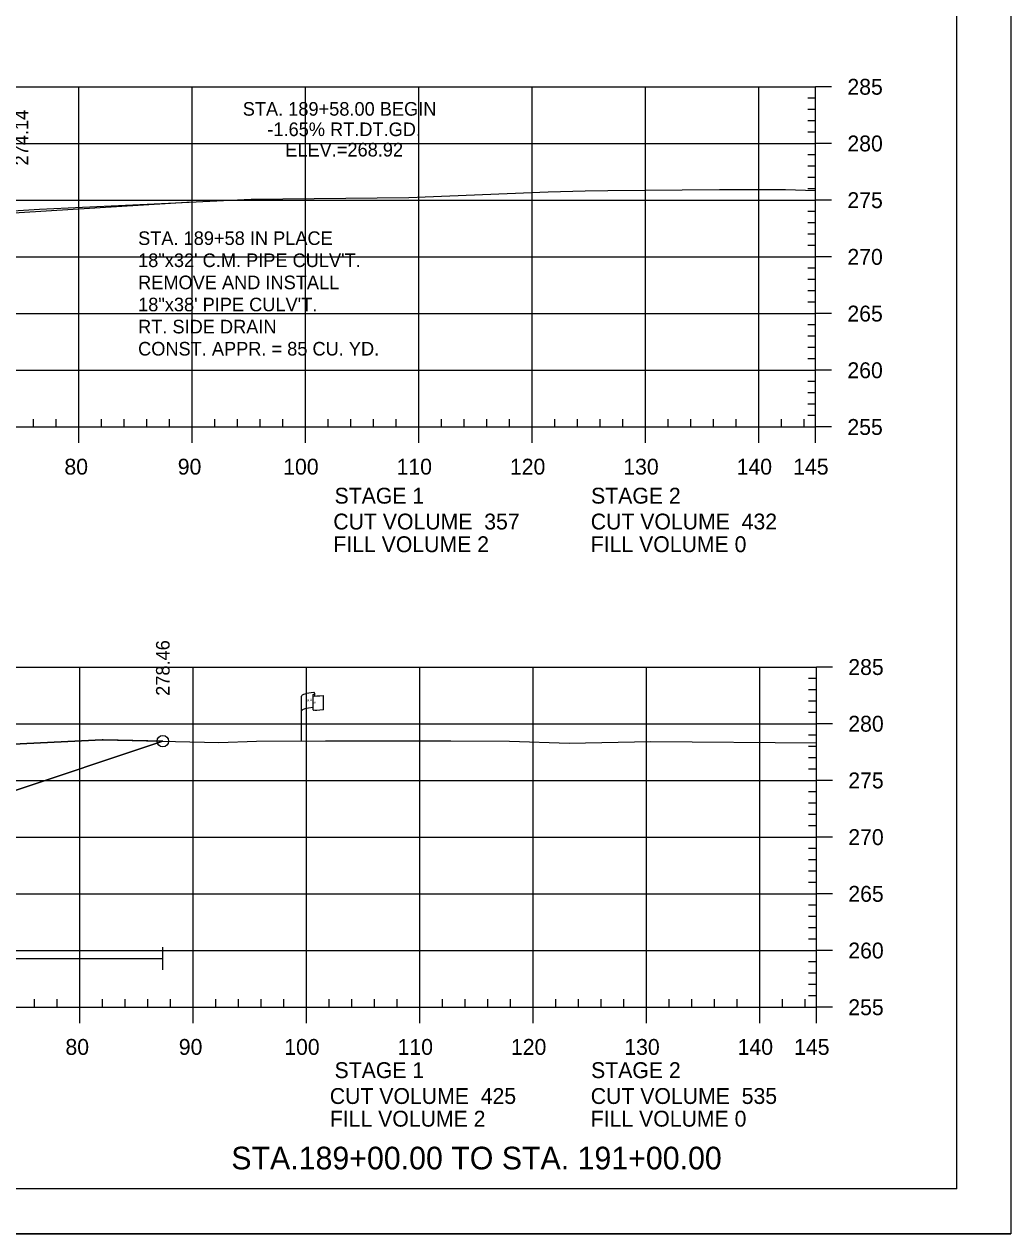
# Model space of a CAD drawing. Extents: x 1365647 to 1367999, y 387113 to 400173.
# Drawn here: x 1365970 to 1366057, y 388866.1 to 388972.8 of the extents above; entities that cross this region are included whole.
import ezdxf

# ---------------------------------------------------------------- set-up
doc = ezdxf.new("R2010")
doc.units = 0
for name, color, linetype in [('E_Existing ROW', 7, 'Continuous'), ('R_Axis', 7, 'Continuous'), ('R_Axis Annot', 7, 'Continuous'), ('R_Border', 7, 'Continuous'), ('R_Contours', 7, 'Continuous'), ('R_Draft', 7, 'Continuous'), ('R_Drive', 7, 'Continuous'), ('R_Exist Surface', 7, 'Continuous'), ('R_Fin Surface', 7, 'Continuous'), ('R_Fin Surface Annot', 7, 'Continuous'), ('R_Grid', 7, 'Continuous'), ('R_No Plot', 7, 'Continuous'), ('R_Proposed Const Limits', 7, 'Continuous'), ('R_Water', 7, 'Continuous')]:
    doc.layers.add(name, color=color, linetype=linetype)

msp = doc.modelspace()

# ---------------------------------------------------------------- linework, layer by layer
at = {"layer": 'E_Existing ROW'}
for p, q in [((1365994.45, 388909.56), (1365994.45, 388913.51)), ((1365995.45, 388913.6), (1365995.45, 388913.59)), ((1365995.45, 388913.59), (1365995.45, 388912.36)), ((1365995.61, 388913.76), (1365995.61, 388913.52)), ((1365996.38, 388913.56), (1365996.38, 388912.32))]:
    msp.add_line(p, q, dxfattribs=at)
for centre, radius, start, end in [((1365995.52, 388913.6), 0.078, 88.6458, 274.2828), ((1365995.54, 388913.76), 0.0783, 263.0712, 93.9564), ((1365995.53, 388912.36), 0.0783, 180, 273.9564)]:
    msp.add_arc(centre, radius, start, end, dxfattribs=at)
for centre, major_axis, ratio, start_param, end_param in [((1365996.03, 388913.55), (-1.58, -0.04), 0.19887, 5.030368, 6.283185), ((1365996.74, 388913.67), (-1.23, -0.13), 0.052933, 0.159456, 1.268315), ((1365996.03, 388912.23), (-1.58, -0.04), 0.19887, 5.083035, 6.194897), ((1365996.74, 388912.43), (-1.23, -0.13), 0.052933, 0.159456, 1.268315)]:
    msp.add_ellipse(centre, major_axis=major_axis, ratio=ratio, start_param=start_param, end_param=end_param, dxfattribs=at)
at = {"layer": 'R_Axis'}
for p, q in [((1366039.81, 388937.25), (1366039.81, 388967.25)), ((1366041.21, 388967.25), (1366039.81, 388967.25)), ((1366039.81, 388966.25), (1366039.11, 388966.25)), ((1366039.81, 388965.25), (1366039.11, 388965.25)), ((1366039.81, 388964.25), (1366039.11, 388964.25)), ((1366039.81, 388963.25), (1366039.11, 388963.25)), ((1366041.21, 388962.25), (1366039.81, 388962.25)), ((1366039.81, 388961.25), (1366039.11, 388961.25)), ((1366039.81, 388960.25), (1366039.11, 388960.25)), ((1366039.81, 388959.25), (1366039.11, 388959.25)), ((1366039.81, 388958.25), (1366039.11, 388958.25)), ((1366041.21, 388957.25), (1366039.81, 388957.25)), ((1366039.81, 388956.25), (1366039.11, 388956.25)), ((1366039.81, 388955.25), (1366039.11, 388955.25)), ((1366039.81, 388954.25), (1366039.11, 388954.25)), ((1366039.81, 388953.25), (1366039.11, 388953.25)), ((1366041.21, 388952.25), (1366039.81, 388952.25)), ((1366039.81, 388951.25), (1366039.11, 388951.25)), ((1366039.81, 388950.25), (1366039.11, 388950.25)), ((1366039.81, 388949.25), (1366039.11, 388949.25)), ((1366039.81, 388948.25), (1366039.11, 388948.25)), ((1366041.21, 388947.25), (1366039.81, 388947.25)), ((1366039.81, 388946.25), (1366039.11, 388946.25)), ((1366039.81, 388945.25), (1366039.11, 388945.25)), ((1366039.81, 388944.25), (1366039.11, 388944.25)), ((1366039.81, 388943.25), (1366039.11, 388943.25)), ((1366041.21, 388942.25), (1366039.81, 388942.25)), ((1366039.81, 388941.25), (1366039.11, 388941.25)), ((1366039.81, 388940.25), (1366039.11, 388940.25)), ((1366039.81, 388939.25), (1366039.11, 388939.25)), ((1365970.81, 388937.25), (1365970.81, 388937.95)), ((1365972.81, 388937.25), (1365972.81, 388937.95)), ((1365976.81, 388937.25), (1365976.81, 388937.95)), ((1365978.81, 388937.25), (1365978.81, 388937.95)), ((1365980.81, 388937.25), (1365980.81, 388937.95)), ((1365982.81, 388937.25), (1365982.81, 388937.95)), ((1365986.81, 388937.25), (1365986.81, 388937.95)), ((1365988.81, 388937.25), (1365988.81, 388937.95)), ((1365990.81, 388937.25), (1365990.81, 388937.95)), ((1365992.81, 388937.25), (1365992.81, 388937.95)), ((1365996.81, 388937.25), (1365996.81, 388937.95)), ((1365998.81, 388937.25), (1365998.81, 388937.95)), ((1366000.81, 388937.25), (1366000.81, 388937.95)), ((1366002.81, 388937.25), (1366002.81, 388937.95)), ((1366006.81, 388937.25), (1366006.81, 388937.95)), ((1366008.81, 388937.25), (1366008.81, 388937.95)), ((1366010.81, 388937.25), (1366010.81, 388937.95)), ((1366012.81, 388937.25), (1366012.81, 388937.95)), ((1366016.81, 388937.25), (1366016.81, 388937.95)), ((1366018.81, 388937.25), (1366018.81, 388937.95)), ((1366020.81, 388937.25), (1366020.81, 388937.95)), ((1366022.81, 388937.25), (1366022.81, 388937.95)), ((1366026.81, 388937.25), (1366026.81, 388937.95)), ((1366028.81, 388937.25), (1366028.81, 388937.95)), ((1366030.81, 388937.25), (1366030.81, 388937.95)), ((1366032.81, 388937.25), (1366032.81, 388937.95)), ((1366036.81, 388937.25), (1366036.81, 388937.95)), ((1366038.81, 388937.25), (1366038.81, 388937.95)), ((1366039.81, 388938.25), (1366039.11, 388938.25)), ((1365749.81, 388937.25), (1366039.81, 388937.25)), ((1365974.81, 388935.85), (1365974.81, 388937.25)), ((1365984.81, 388935.85), (1365984.81, 388937.25)), ((1365994.81, 388935.85), (1365994.81, 388937.25)), ((1366004.81, 388935.85), (1366004.81, 388937.25)), ((1366014.81, 388935.85), (1366014.81, 388937.25)), ((1366024.81, 388935.85), (1366024.81, 388937.25)), ((1366034.81, 388935.85), (1366034.81, 388937.25)), ((1366039.81, 388935.85), (1366039.81, 388937.25)), ((1366041.21, 388937.25), (1366039.81, 388937.25)), ((1366039.89, 388886.08), (1366039.89, 388916.08)), ((1366041.29, 388916.08), (1366039.89, 388916.08)), ((1366039.89, 388915.08), (1366039.19, 388915.08)), ((1366039.89, 388914.08), (1366039.19, 388914.08)), ((1366039.89, 388913.08), (1366039.19, 388913.08)), ((1366039.89, 388912.08), (1366039.19, 388912.08)), ((1366041.29, 388911.08), (1366039.89, 388911.08)), ((1366039.89, 388910.08), (1366039.19, 388910.08)), ((1366039.89, 388909.08), (1366039.19, 388909.08)), ((1366039.89, 388908.08), (1366039.19, 388908.08)), ((1366039.89, 388907.08), (1366039.19, 388907.08)), ((1366041.29, 388906.08), (1366039.89, 388906.08)), ((1366039.89, 388905.08), (1366039.19, 388905.08)), ((1366039.89, 388904.08), (1366039.19, 388904.08)), ((1366039.89, 388903.08), (1366039.19, 388903.08)), ((1366039.89, 388902.08), (1366039.19, 388902.08)), ((1366041.29, 388901.08), (1366039.89, 388901.08)), ((1366039.89, 388900.08), (1366039.19, 388900.08)), ((1366039.89, 388899.08), (1366039.19, 388899.08)), ((1366039.89, 388898.08), (1366039.19, 388898.08)), ((1366039.89, 388897.08), (1366039.19, 388897.08)), ((1366041.29, 388896.08), (1366039.89, 388896.08)), ((1366039.89, 388895.08), (1366039.19, 388895.08)), ((1366039.89, 388894.08), (1366039.19, 388894.08)), ((1366039.89, 388893.08), (1366039.19, 388893.08)), ((1366039.89, 388892.08), (1366039.19, 388892.08)), ((1366041.29, 388891.08), (1366039.89, 388891.08)), ((1366039.89, 388890.08), (1366039.19, 388890.08)), ((1366039.89, 388889.08), (1366039.19, 388889.08)), ((1366039.89, 388888.08), (1366039.19, 388888.08)), ((1365970.89, 388886.08), (1365970.89, 388886.78)), ((1365972.89, 388886.08), (1365972.89, 388886.78)), ((1365976.89, 388886.08), (1365976.89, 388886.78)), ((1365978.89, 388886.08), (1365978.89, 388886.78)), ((1365980.89, 388886.08), (1365980.89, 388886.78)), ((1365982.89, 388886.08), (1365982.89, 388886.78)), ((1365986.89, 388886.08), (1365986.89, 388886.78)), ((1365988.89, 388886.08), (1365988.89, 388886.78)), ((1365990.89, 388886.08), (1365990.89, 388886.78)), ((1365992.89, 388886.08), (1365992.89, 388886.78)), ((1365996.89, 388886.08), (1365996.89, 388886.78)), ((1365998.89, 388886.08), (1365998.89, 388886.78)), ((1366000.89, 388886.08), (1366000.89, 388886.78)), ((1366002.89, 388886.08), (1366002.89, 388886.78)), ((1366006.89, 388886.08), (1366006.89, 388886.78)), ((1366008.89, 388886.08), (1366008.89, 388886.78)), ((1366010.89, 388886.08), (1366010.89, 388886.78)), ((1366012.89, 388886.08), (1366012.89, 388886.78)), ((1366016.89, 388886.08), (1366016.89, 388886.78)), ((1366018.89, 388886.08), (1366018.89, 388886.78)), ((1366020.89, 388886.08), (1366020.89, 388886.78)), ((1366022.89, 388886.08), (1366022.89, 388886.78)), ((1366026.89, 388886.08), (1366026.89, 388886.78)), ((1366028.89, 388886.08), (1366028.89, 388886.78)), ((1366030.89, 388886.08), (1366030.89, 388886.78)), ((1366032.89, 388886.08), (1366032.89, 388886.78)), ((1366036.89, 388886.08), (1366036.89, 388886.78)), ((1366038.89, 388886.08), (1366038.89, 388886.78)), ((1366039.89, 388887.08), (1366039.19, 388887.08)), ((1365749.89, 388886.08), (1366039.89, 388886.08)), ((1365974.89, 388884.68), (1365974.89, 388886.08)), ((1365984.89, 388884.68), (1365984.89, 388886.08)), ((1365994.89, 388884.68), (1365994.89, 388886.08)), ((1366004.89, 388884.68), (1366004.89, 388886.08)), ((1366014.89, 388884.68), (1366014.89, 388886.08)), ((1366024.89, 388884.68), (1366024.89, 388886.08)), ((1366034.89, 388884.68), (1366034.89, 388886.08)), ((1366039.89, 388884.68), (1366039.89, 388886.08)), ((1366041.29, 388886.08), (1366039.89, 388886.08))]:
    msp.add_line(p, q, dxfattribs=at)
at = {"layer": 'R_Border'}
for q in [(1366052.27, 389075.54), (1365736.09, 388870.08)]:
    msp.add_line((1366052.27, 388870.08), q, dxfattribs=at)
at = {"layer": 'R_Contours'}
msp.add_line((1365982.22, 388909.54), (1365976.97, 388909.65), dxfattribs=at)
msp.add_lwpolyline([(1365927.05, 388902.69), (1365927.14, 388902.71), (1365929.49, 388903.28), (1365934.03, 388904.39), (1365942.29, 388905.41), (1365942.8, 388905.47), (1365946.8, 388906.16), (1365963.96, 388909.17), (1365969.03, 388909.29), (1365976.87, 388909.65), (1365976.94, 388909.65), (1365976.97, 388909.65), (1365982.22, 388909.54), (1365954.38, 388900.26), (1365941.51, 388902.41)], close=True, dxfattribs=at)
for points in [[(1365976.97, 388909.65), (1365976.94, 388909.65), (1365976.87, 388909.65), (1365969.03, 388909.29), (1365963.96, 388909.17), (1365946.8, 388906.16), (1365942.8, 388905.47), (1365942.29, 388905.41), (1365934.03, 388904.39), (1365932.18, 388903.93)], [(1365932.38, 388903.93), (1365941.51, 388902.41), (1365954.38, 388900.26), (1365982.22, 388909.54)], [(1365982.22, 388909.54), (1365982.22, 388909.54)]]:
    msp.add_lwpolyline(points, dxfattribs=at)
at = {"layer": 'R_Drive'}
msp.add_line((1365949.29, 388954.95), (1365984.81, 388957.09), dxfattribs=at)
at = {"layer": 'R_Exist Surface'}
for points in [[(1365961.93, 388955.88), (1365971.34, 388956.47), (1365982.72, 388956.99), (1365990.01, 388957.34), (1366003.91, 388957.5), (1366016.2, 388957.99), (1366019.49, 388958.06), (1366021.49, 388958.11), (1366031.33, 388958.2), (1366037.15, 388958.18), (1366039.81, 388958.11)], [(1365969.03, 388909.29), (1365976.87, 388909.65), (1365976.94, 388909.65), (1365976.97, 388909.65), (1365987.17, 388909.43), (1365990.47, 388909.55), (1365996.58, 388909.56), (1366007.63, 388909.56), (1366012.79, 388909.54), (1366018.08, 388909.38), (1366025.27, 388909.52), (1366039.89, 388909.4)]]:
    msp.add_lwpolyline(points, dxfattribs=at)
at = {"layer": 'R_Fin Surface'}
msp.add_lwpolyline([(1365804.83, 388906.43), (1365829.36, 388898.25), (1365835.38, 388900.26), (1365848.26, 388902.41), (1365857.38, 388903.93), (1365863.38, 388904.17), (1365865.38, 388904.21), (1365894.88, 388904.8), (1365924.38, 388904.21), (1365926.38, 388904.17), (1365932.38, 388903.93), (1365941.51, 388902.41), (1365954.38, 388900.26), (1365982.22, 388909.54)], dxfattribs=at)
at = {"layer": 'R_Grid'}
for p, q in [((1365749.81, 388967.25), (1366039.81, 388967.25)), ((1365974.81, 388937.25), (1365974.81, 388967.25)), ((1365984.81, 388937.25), (1365984.81, 388967.25)), ((1365994.81, 388937.25), (1365994.81, 388967.25)), ((1366004.81, 388937.25), (1366004.81, 388967.25)), ((1366014.81, 388937.25), (1366014.81, 388967.25)), ((1366024.81, 388937.25), (1366024.81, 388967.25)), ((1366034.81, 388937.25), (1366034.81, 388967.25)), ((1366039.81, 388937.25), (1366039.81, 388967.25)), ((1365749.81, 388962.25), (1366039.81, 388962.25)), ((1365749.81, 388957.25), (1366039.81, 388957.25)), ((1365749.81, 388952.25), (1366039.81, 388952.25)), ((1365749.81, 388947.25), (1366039.81, 388947.25)), ((1365749.81, 388942.25), (1366039.81, 388942.25)), ((1365749.81, 388937.25), (1366039.81, 388937.25)), ((1365749.89, 388916.08), (1366039.89, 388916.08)), ((1365974.89, 388886.08), (1365974.89, 388916.08)), ((1365984.89, 388886.08), (1365984.89, 388916.08)), ((1365994.89, 388886.08), (1365994.89, 388916.08)), ((1366004.89, 388886.08), (1366004.89, 388916.08)), ((1366014.89, 388886.08), (1366014.89, 388916.08)), ((1366024.89, 388886.08), (1366024.89, 388916.08)), ((1366034.89, 388886.08), (1366034.89, 388916.08)), ((1366039.89, 388886.08), (1366039.89, 388916.08)), ((1365749.89, 388911.08), (1366039.89, 388911.08)), ((1365749.89, 388906.08), (1366039.89, 388906.08)), ((1365749.89, 388901.08), (1366039.89, 388901.08)), ((1365749.89, 388896.08), (1366039.89, 388896.08)), ((1365749.89, 388891.08), (1366039.89, 388891.08)), ((1365749.89, 388886.08), (1366039.89, 388886.08))]:
    msp.add_line(p, q, dxfattribs=at)
at = {"layer": 'R_No Plot'}
msp.add_line((1365723.69, 388866.1), (1366057.03, 388866.1), dxfattribs=at)
msp.add_lwpolyline([(1365723.69, 389079.44), (1366057.03, 389079.44), (1366057.03, 388866.1), (1365723.69, 388866.1)], close=True, dxfattribs=at)
msp.add_circle((1365982.22, 388909.54), 0.5, dxfattribs=at)
msp.add_circle((1365982.22, 388909.54), 0.5, dxfattribs=at)
at = {"layer": 'R_Proposed Const Limits'}
msp.add_lwpolyline([(1365932.38, 388903.93), (1365954.38, 388900.26), (1365982.22, 388909.54)], dxfattribs=at)
at = {"layer": 'R_Water'}
for p, q in [((1365982.22, 388889.37), (1365982.22, 388891.37)), ((1365883.15, 388890.37), (1365982.22, 388890.37))]:
    msp.add_line(p, q, dxfattribs=at)

# ---------------------------------------------------------------- texts
at = {"layer": 'E_Existing ROW'}
for s, height, rotation, p in [('DWB 11-9-07', 0.001, 90, (1365995.61, 388913.52)), ('R ', 0.2, 9.9884, (1365994.97, 388913.01)), (' O', 0.2, 9.9884, (1365995.12, 388913.05)), ('W', 0.2, 351.1788, (1365995.45, 388912.88)), ('DWB 11-9-07', 0.001, 5.0717, (1365996.37, 388912.32)), ('DWB 11-9-07', 0.001, 90, (1365994.45, 388909.56))]:
    msp.add_text(s, height=height, rotation=rotation, dxfattribs=at).set_placement(p)
at = {"layer": 'R_Axis Annot'}
for s, p in [('285', (1366042.61, 388966.55)), ('280', (1366042.61, 388961.55)), ('275', (1366042.61, 388956.55)), ('270', (1366042.61, 388951.55)), ('265', (1366042.61, 388946.55)), ('260', (1366042.61, 388941.55)), ('255', (1366042.61, 388936.55)), ('80', (1365973.54, 388933.05)), ('90', (1365983.54, 388933.05)), ('100', (1365992.84, 388933.05)), ('110', (1366002.84, 388933.05)), ('120', (1366012.84, 388933.05)), ('130', (1366022.84, 388933.05)), ('140', (1366032.84, 388933.05)), ('145', (1366037.83, 388933.05)), ('STAGE 1', (1365997.37, 388930.49)), ('STAGE 2', (1366020, 388930.49)), ('CUT VOLUME  357', (1365997.26, 388928.21)), ('CUT VOLUME  432', (1366019.97, 388928.21)), ('FILL VOLUME 2', (1365997.26, 388926.21)), ('FILL VOLUME 0', (1366019.97, 388926.21)), ('285', (1366042.69, 388915.38)), ('280', (1366042.69, 388910.38)), ('275', (1366042.69, 388905.38)), ('270', (1366042.69, 388900.38)), ('265', (1366042.69, 388895.38)), ('260', (1366042.69, 388890.38)), ('255', (1366042.69, 388885.38)), ('80', (1365973.63, 388881.88)), ('90', (1365983.63, 388881.88)), ('100', (1365992.93, 388881.88)), ('110', (1366002.93, 388881.88)), ('120', (1366012.93, 388881.88)), ('130', (1366022.93, 388881.88)), ('140', (1366032.93, 388881.88)), ('145', (1366037.91, 388881.88)), ('STAGE 1', (1365997.37, 388879.83)), ('STAGE 2', (1366020, 388879.83)), ('CUT VOLUME  425', (1365996.95, 388877.55)), ('CUT VOLUME  535', (1366019.97, 388877.55)), ('FILL VOLUME 2', (1365996.95, 388875.55)), ('FILL VOLUME 0', (1366019.97, 388875.55))]:
    msp.add_text(s, height=1.4, dxfattribs=at).set_placement(p)
at = {"layer": 'R_Draft'}
for s, p in [('STA. 189+58 IN PLACE', (1365980.04, 388953.3)), ('18"x32\' C.M. PIPE CULV\'T.', (1365980.04, 388951.35)), ('REMOVE AND INSTALL ', (1365980.04, 388949.4)), ('18"x38\' PIPE CULV\'T.', (1365980.04, 388947.45)), ('RT. SIDE DRAIN', (1365980.04, 388945.5)), ('CONST. APPR. = 85 CU. YD.', (1365980.04, 388943.55))]:
    msp.add_text(s, height=1.2, rotation=360, dxfattribs=at).set_placement(p)
msp.add_text('STA.189+00.00 TO STA. 191+00.00', height=2, dxfattribs=at).set_placement((1365988.26, 388871.78))
at = {"layer": 'R_Fin Surface Annot'}
for s, p in [('274.14', (1365970.35, 388960.31)), ('278.46', (1365982.82, 388913.54))]:
    msp.add_text(s, height=1.2, rotation=90, dxfattribs=at).set_placement(p)
at = {"layer": 'R_Water'}
for s, p in [('STA. 189+58.00 BEGIN', (1365989.27, 388964.7)), ('-1.65% RT.DT.GD.', (1365991.44, 388962.9)), ('ELEV.=268.92', (1365993.02, 388961.1))]:
    msp.add_text(s, height=1.2, dxfattribs=at).set_placement(p)

doc.saveas('drawing.dxf')
